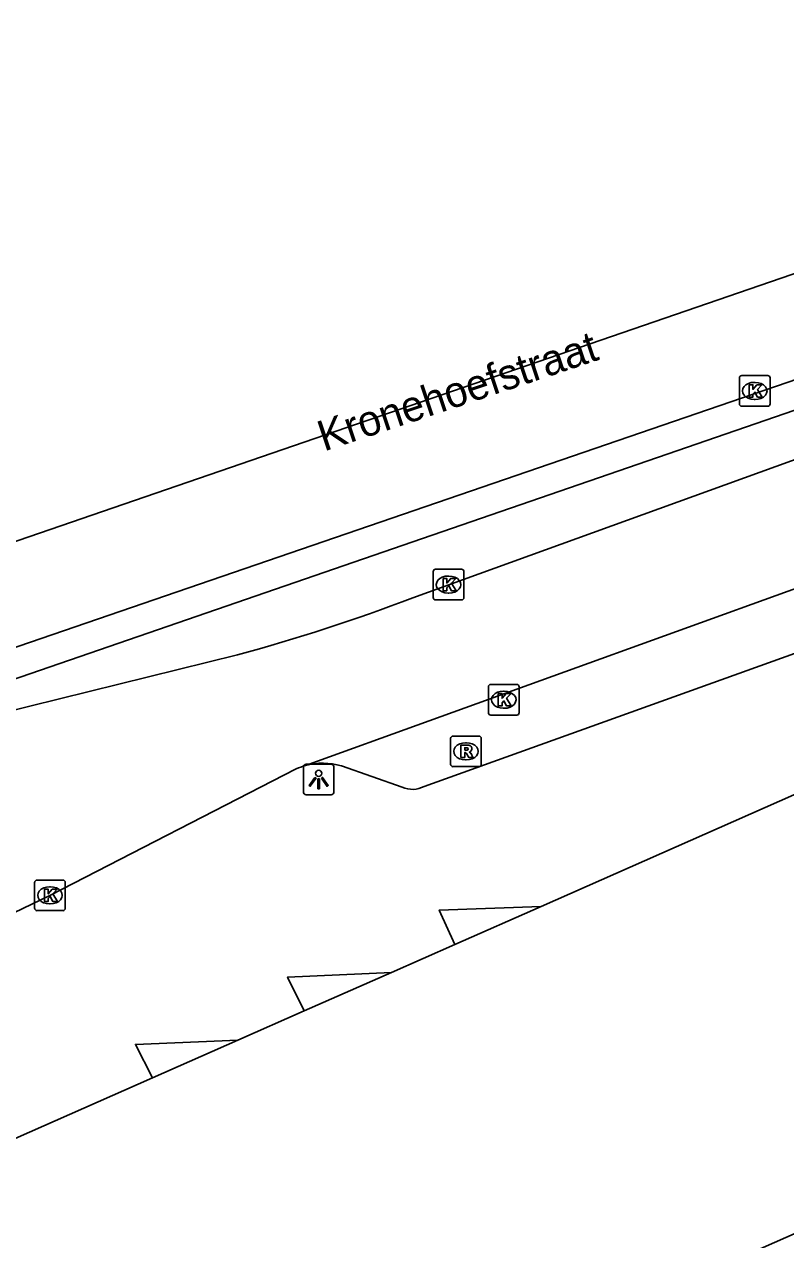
# Model space of a CAD drawing. Extents: x 160379 to 161131, y 383940 to 384849.
# Drawn here: x 160440.93 to 160465.79, y 384747.46 to 384787.15 of the extents above; entities that cross this region are included whole.
import ezdxf

# ---------------------------------------------------------------- set-up
doc = ezdxf.new("R2010")
doc.units = 0
for name, color, linetype in [('IMGEO_Berm_open', 7, 'Continuous'), ('IMGEO_Kolk', 7, 'Continuous'), ('IMGEO_Lichtpunt', 7, 'Continuous'), ('IMGEO_Openbare_ruimte_label', 7, 'Continuous'), ('IMGEO_Pand', 7, 'Continuous'), ('IMGEO_Pand_overbouw', 7, 'Continuous'), ('IMGEO_Rijbaan_lokaal_gesloten', 7, 'Continuous'), ('IMGEO_Rijbaan_regionaal_gesloten', 7, 'Continuous'), ('IMGEO_Rioolput', 7, 'Continuous'), ('IMGEO_Voetpad_open', 7, 'Continuous')]:
    doc.layers.add(name, color=color, linetype=linetype)

msp = doc.modelspace()

# ---------------------------------------------------------------- linework, layer by layer
at = {"layer": 'IMGEO_Berm_open'}
msp.add_lwpolyline([(160440.136, 384764.646), (160439.839, 384765.507), (160495.523, 384784.69)], dxfattribs=at)
at = {"layer": 'IMGEO_Kolk'}
for p, q in [((160464.281, 384774.749), (160464.281, 384775.601)), ((160464.356, 384775.675), (160465.208, 384775.675)), ((160465.282, 384775.601), (160465.282, 384774.749)), ((160464.769, 384775.455), (160464.794, 384775.455)), ((160464.792, 384774.895), (160464.767, 384774.895)), ((160465.208, 384774.675), (160464.356, 384774.675)), ((160454.284, 384768.425), (160454.284, 384769.277)), ((160454.359, 384769.351), (160455.211, 384769.351)), ((160455.285, 384769.277), (160455.285, 384768.425)), ((160454.772, 384769.131), (160454.797, 384769.131)), ((160454.795, 384768.571), (160454.77, 384768.571)), ((160455.211, 384768.351), (160454.359, 384768.351)), ((160456.087, 384764.666), (160456.087, 384765.518)), ((160456.162, 384765.592), (160457.014, 384765.592)), ((160456.575, 384765.372), (160456.6, 384765.372)), ((160457.088, 384765.518), (160457.088, 384764.666)), ((160457.014, 384764.592), (160456.162, 384764.592)), ((160456.598, 384764.812), (160456.573, 384764.812)), ((160441.27, 384758.279), (160441.27, 384759.131)), ((160441.345, 384759.205), (160442.197, 384759.205)), ((160441.758, 384758.985), (160441.783, 384758.985)), ((160442.271, 384759.131), (160442.271, 384758.279)), ((160442.197, 384758.205), (160441.345, 384758.205)), ((160441.781, 384758.425), (160441.756, 384758.425))]:
    msp.add_line(p, q, dxfattribs=at)
for points in [[(160464.281, 384774.749), (160464.281, 384775.601)], [(160464.356, 384775.675), (160465.208, 384775.675)], [(160465.282, 384775.601), (160465.282, 384774.749)], [(160464.602, 384775.375), (160464.725, 384775.375), (160464.725, 384775.224), (160464.855, 384775.375), (160465.019, 384775.375), (160464.873, 384775.224), (160465.026, 384774.975), (160464.874, 384774.975), (160464.789, 384775.139), (160464.725, 384775.072), (160464.725, 384774.975), (160464.602, 384774.975), (160464.602, 384775.375)], [(160465.208, 384774.675), (160464.356, 384774.675)], [(160454.284, 384768.425), (160454.284, 384769.277)], [(160454.359, 384769.351), (160455.211, 384769.351)], [(160455.285, 384769.277), (160455.285, 384768.425)], [(160454.605, 384769.051), (160454.728, 384769.051), (160454.728, 384768.9), (160454.858, 384769.051), (160455.022, 384769.051), (160454.876, 384768.9), (160455.029, 384768.651), (160454.877, 384768.651), (160454.792, 384768.815), (160454.728, 384768.748), (160454.728, 384768.651), (160454.605, 384768.651), (160454.605, 384769.051)], [(160455.211, 384768.351), (160454.359, 384768.351)], [(160456.087, 384764.666), (160456.087, 384765.518)], [(160456.162, 384765.592), (160457.014, 384765.592)], [(160456.408, 384765.292), (160456.531, 384765.292), (160456.531, 384765.141), (160456.661, 384765.292), (160456.825, 384765.292), (160456.679, 384765.141), (160456.832, 384764.892), (160456.68, 384764.892), (160456.595, 384765.056), (160456.531, 384764.989), (160456.531, 384764.892), (160456.408, 384764.892), (160456.408, 384765.292)], [(160457.088, 384765.518), (160457.088, 384764.666)], [(160457.014, 384764.592), (160456.162, 384764.592)], [(160441.27, 384758.279), (160441.27, 384759.131)], [(160441.345, 384759.205), (160442.197, 384759.205)], [(160441.591, 384758.905), (160441.714, 384758.905), (160441.714, 384758.754), (160441.844, 384758.905), (160442.008, 384758.905), (160441.862, 384758.754), (160442.015, 384758.505), (160441.863, 384758.505), (160441.778, 384758.669), (160441.714, 384758.602), (160441.714, 384758.505), (160441.591, 384758.505), (160441.591, 384758.905)], [(160442.271, 384759.131), (160442.271, 384758.279)], [(160442.197, 384758.205), (160441.345, 384758.205)]]:
    msp.add_lwpolyline(points, dxfattribs=at)
for centre, start, end in [((160464.358, 384775.599), 91.552, 178.448), ((160464.358, 384775.599), 91.552, 178.448), ((160465.206, 384775.599), 1.552, 88.448), ((160465.206, 384775.599), 1.552, 88.448), ((160464.358, 384774.751), 181.552, 268.448), ((160464.358, 384774.751), 181.552, 268.448), ((160465.206, 384774.751), 271.552, 358.448), ((160465.206, 384774.751), 271.552, 358.448), ((160454.361, 384769.275), 91.552, 178.448), ((160454.361, 384769.275), 91.552, 178.448), ((160455.209, 384769.275), 1.552, 88.448), ((160455.209, 384769.275), 1.552, 88.448), ((160454.361, 384768.427), 181.552, 268.448), ((160454.361, 384768.427), 181.552, 268.448), ((160455.209, 384768.427), 271.552, 358.448), ((160455.209, 384768.427), 271.552, 358.448), ((160456.164, 384765.516), 91.552, 178.448), ((160456.164, 384765.516), 91.552, 178.448), ((160457.012, 384765.516), 1.552, 88.448), ((160457.012, 384765.516), 1.552, 88.448), ((160456.164, 384764.668), 181.552, 268.448), ((160456.164, 384764.668), 181.552, 268.448), ((160457.012, 384764.668), 271.552, 358.448), ((160457.012, 384764.668), 271.552, 358.448), ((160441.347, 384759.129), 91.552, 178.448), ((160441.347, 384759.129), 91.552, 178.448), ((160442.195, 384759.129), 1.552, 88.448), ((160442.195, 384759.129), 1.552, 88.448), ((160441.347, 384758.281), 181.552, 268.448), ((160441.347, 384758.281), 181.552, 268.448), ((160442.195, 384758.281), 271.552, 358.448), ((160442.195, 384758.281), 271.552, 358.448)]:
    msp.add_arc(centre, 0.0765, start, end, dxfattribs=at)
for centre, major_axis, ratio, start_param, end_param in [((160464.768, 384775.175), (-0.387, 0.002), 0.722429, 4.712389, 7.853982), ((160464.793, 384775.175), (-0.39, 0.002), 0.717154, 1.570796, 4.712389), ((160454.771, 384768.851), (-0.387, 0.002), 0.722429, 4.712389, 7.853982), ((160454.796, 384768.851), (-0.39, 0.002), 0.717154, 1.570796, 4.712389), ((160456.574, 384765.092), (-0.387, 0.002), 0.722429, 4.712389, 7.853982), ((160456.599, 384765.092), (-0.39, 0.002), 0.717154, 1.570796, 4.712389), ((160441.757, 384758.705), (-0.387, 0.002), 0.722429, 4.712389, 7.853982), ((160441.782, 384758.705), (-0.39, 0.002), 0.717154, 1.570796, 4.712389)]:
    msp.add_ellipse(centre, major_axis=major_axis, ratio=ratio, start_param=start_param, end_param=end_param, dxfattribs=at)
at = {"layer": 'IMGEO_Lichtpunt'}
for p, q in [((160450.045, 384762.891), (160450.045, 384762.084)), ((160450.045, 384762.891), (160450.045, 384762.084)), ((160450.947, 384762.986), (160450.139, 384762.986)), ((160450.947, 384762.986), (160450.139, 384762.986)), ((160451.041, 384762.084), (160451.041, 384762.891)), ((160451.041, 384762.084), (160451.041, 384762.891)), ((160450.139, 384761.99), (160450.947, 384761.99)), ((160450.139, 384761.99), (160450.947, 384761.99))]:
    msp.add_line(p, q, dxfattribs=at)
for points in [[(160450.419, 384762.555), (160450.458, 384762.527), (160450.27, 384762.265), (160450.232, 384762.292), (160450.419, 384762.555)], [(160450.521, 384762.507), (160450.568, 384762.507), (160450.568, 384762.185), (160450.521, 384762.185), (160450.521, 384762.507)], [(160450.631, 384762.527), (160450.669, 384762.554), (160450.856, 384762.292), (160450.817, 384762.264), (160450.631, 384762.527)]]:
    msp.add_lwpolyline(points, dxfattribs=at)
msp.add_circle((160450.544, 384762.689), 0.0994, dxfattribs=at)
for centre, start, end in [((160450.139, 384762.891), 90, 180), ((160450.139, 384762.891), 90, 180), ((160450.947, 384762.891), 0, 90), ((160450.947, 384762.891), 0, 90), ((160450.139, 384762.084), 180, 270), ((160450.139, 384762.084), 180, 270), ((160450.947, 384762.084), 270, 0), ((160450.947, 384762.084), 270, 360)]:
    msp.add_arc(centre, 0.0946, start, end, dxfattribs=at)
at = {"layer": 'IMGEO_Pand'}
for points in [[(160489.562, 384772.388), (160490.306, 384767.006), (160491.558, 384767.562), (160491.505, 384767.959), (160491.915, 384768.014), (160493.106, 384759.485), (160474.704, 384751.423), (160471.395, 384750), (160438.007, 384735.266)], [(160489.562, 384772.388), (160474.338, 384765.646), (160474.703, 384764.823), (160468.722, 384761.279), (160468.028, 384762.853), (160457.806, 384758.343)], [(160457.806, 384758.343), (160454.991, 384757.101)], [(160454.991, 384757.101), (160452.92, 384756.187)], [(160452.92, 384756.187), (160450.07, 384754.929)], [(160450.07, 384754.929), (160447.903, 384753.973)], [(160447.903, 384753.973), (160445.12, 384752.745)], [(160445.12, 384752.745), (160424.929, 384743.835)]]:
    msp.add_lwpolyline(points, dxfattribs=at)
at = {"layer": 'IMGEO_Pand_overbouw'}
for points in [[(160457.806, 384758.343), (160454.483, 384758.223), (160454.991, 384757.101)], [(160450.07, 384754.929), (160452.92, 384756.187), (160449.529, 384756.036)], [(160445.12, 384752.745), (160447.903, 384753.973), (160444.559, 384753.84)]]:
    msp.add_lwpolyline(points, close=True, dxfattribs=at)
at = {"layer": 'IMGEO_Rijbaan_lokaal_gesloten'}
for points in [[(160499.676, 384785.009), (160494.018, 384783.035), (160453.622, 384768.421)], [(160486.46, 384776.07), (160450.109, 384762.942)], [(160447.891, 384766.557), (160440.136, 384764.646)], [(160440.594, 384758.136), (160441.771, 384758.705), (160449.81, 384762.834)]]:
    msp.add_lwpolyline(points, dxfattribs=at)
for centre, radius, start, end in [((160432.036, 384825.046), 60.6, 285.16692, 290.86717), ((160450.619, 384761.061), 1.949, 105.182, 114.5378)]:
    msp.add_arc(centre, radius, start, end, dxfattribs=at)
at = {"layer": 'IMGEO_Rijbaan_regionaal_gesloten'}
for points in [[(160407.774, 384758.961), (160496.29, 384789.397), (160509.787, 384793.209), (160516.634, 384794.476), (160522.145, 384795.098), (160533.464, 384796.44), (160578.535, 384797.637), (160591.993, 384798.377), (160620.019, 384800.647), (160623.941, 384800.965), (160636.271, 384802.448), (160652.633, 384805.11), (160663.941, 384807.107), (160687.886, 384811.633), (160723.538, 384818.688), (160757.394, 384825.337), (160773.567, 384827.732), (160796.581, 384831.06), (160808.154, 384832.524), (160820.659, 384834.653), (160832.812, 384837.187)], [(160429.887, 384763.079), (160435.571, 384765.062), (160466.954, 384775.834), (160495.842, 384785.776)]]:
    msp.add_lwpolyline(points, dxfattribs=at)
at = {"layer": 'IMGEO_Rioolput'}
for p, q in [((160454.853, 384762.981), (160454.853, 384763.833)), ((160454.928, 384763.907), (160455.78, 384763.907)), ((160455.341, 384763.687), (160455.366, 384763.687)), ((160455.854, 384763.833), (160455.854, 384762.981)), ((160455.78, 384762.907), (160454.928, 384762.907)), ((160455.364, 384763.127), (160455.339, 384763.127))]:
    msp.add_line(p, q, dxfattribs=at)
for points in [[(160454.853, 384762.981), (160454.853, 384763.833)], [(160454.928, 384763.907), (160455.78, 384763.907)], [(160455.854, 384763.833), (160455.854, 384762.981)], [(160455.442, 384763.605), (160455.19, 384763.607), (160455.19, 384763.207)], [(160455.19, 384763.207), (160455.314, 384763.207), (160455.314, 384763.369), (160455.325, 384763.369)], [(160455.368, 384763.526), (160455.314, 384763.526), (160455.314, 384763.445)], [(160455.314, 384763.445), (160455.366, 384763.445)], [(160455.372, 384763.34), (160455.443, 384763.207), (160455.583, 384763.207), (160455.518, 384763.333)], [(160455.78, 384762.907), (160454.928, 384762.907)]]:
    msp.add_lwpolyline(points, dxfattribs=at)
for centre, radius, start, end in [((160454.93, 384763.831), 0.0765, 91.552, 178.448), ((160454.93, 384763.831), 0.0765, 91.552, 178.448), ((160455.778, 384763.831), 0.0765, 1.552, 88.448), ((160455.778, 384763.831), 0.0765, 1.552, 88.448), ((160455.324, 384763.316), 0.0533, 26.0293, 88.6989), ((160455.35, 384763.634), 0.19, 274.7715, 282.9687), ((160455.374, 384763.43), 0.0964, 77.0061, 93.1865), ((160455.388, 384763.487), 0.0378, 276.6634, 79.6772), ((160455.441, 384763.495), 0.109, 350.3612, 89.416), ((160455.439, 384763.495), 0.112, 277.5842, 350.9817), ((160455.423, 384763.28), 0.108, 29.5134, 73.7905), ((160454.93, 384762.983), 0.0765, 181.552, 268.448), ((160454.93, 384762.983), 0.0765, 181.552, 268.448), ((160455.778, 384762.983), 0.0765, 271.552, 358.448), ((160455.778, 384762.983), 0.0765, 271.552, 358.448)]:
    msp.add_arc(centre, radius, start, end, dxfattribs=at)
for centre, major_axis, ratio, start_param, end_param in [((160455.34, 384763.407), (-0.387, 0.002), 0.722429, 4.712389, 7.853982), ((160455.365, 384763.407), (-0.39, 0.002), 0.717154, 1.570796, 4.712389)]:
    msp.add_ellipse(centre, major_axis=major_axis, ratio=ratio, start_param=start_param, end_param=end_param, dxfattribs=at)
at = {"layer": 'IMGEO_Voetpad_open'}
for points in [[(160453.992, 384762.264), (160484.081, 384773.066)], [(160451.285, 384762.934), (160453.271, 384762.24)], [(160457.806, 384758.343), (160454.483, 384758.223), (160454.991, 384757.101)], [(160452.92, 384756.187), (160449.529, 384756.036), (160450.07, 384754.929)], [(160447.903, 384753.973), (160444.559, 384753.84), (160445.12, 384752.745)]]:
    msp.add_lwpolyline(points, dxfattribs=at)
for centre, radius, start, end in [((160450.683, 384760.884), 2.136, 73.6347, 105.5858), ((160453.608, 384762.968), 0.802, 245.1664, 298.6466)]:
    msp.add_arc(centre, radius, start, end, dxfattribs=at)

# ---------------------------------------------------------------- texts
at = {"layer": 'IMGEO_Openbare_ruimte_label'}
msp.add_text('Kronehoefstraat', height=1, rotation=18.4712, dxfattribs=at).set_placement((160450.718, 384773.192))

doc.saveas('drawing.dxf')
